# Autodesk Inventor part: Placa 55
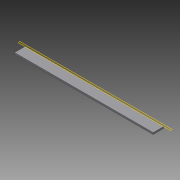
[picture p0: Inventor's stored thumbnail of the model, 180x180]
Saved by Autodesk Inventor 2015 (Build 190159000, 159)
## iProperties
Created: 2015-04
Part Number: Placa 55
Material: Generic
Document SubType Name: Modeling
Designer: suporte
Density: 1 g/cm^3
Appearance: Default
Author: suporte
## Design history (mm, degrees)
workplane "Work Plane1"
sketch "Sketch1"
  geometry: L1 (-996.243, 0)-(0, 0) reference; L2 (-996.243, 0)-(-996.243, -12.5) reference; L3 (0, -12.5)-(-996.243, -12.5) reference; L4 (0, 0)-(0, -12.5) reference; L5 (0, -87.5)-(-996.243, -87.5); L6 (-996.243, -87.5)-(-996.243, -12.5); L7 (-996.243, -12.5)-(0, -12.5); L8 (0, -12.5)-(0, -87.5)
  constraints: 8 end point, 2 parallel, 1 horizontal, 1 perpendicular, 1 other
extrude "Extrusion1" new body sketch "Sketch1" distance "d0" = 12.5; taper "d1" = 0 deg
body "Solid1"
node "Reference1"
